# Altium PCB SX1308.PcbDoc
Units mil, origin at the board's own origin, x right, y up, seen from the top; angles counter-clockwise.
Board outline 685 x 570 mil, 2 copper layers (Top Layer, Bottom Layer); 13 components, 7 nets, 30 pads, 24 vias.
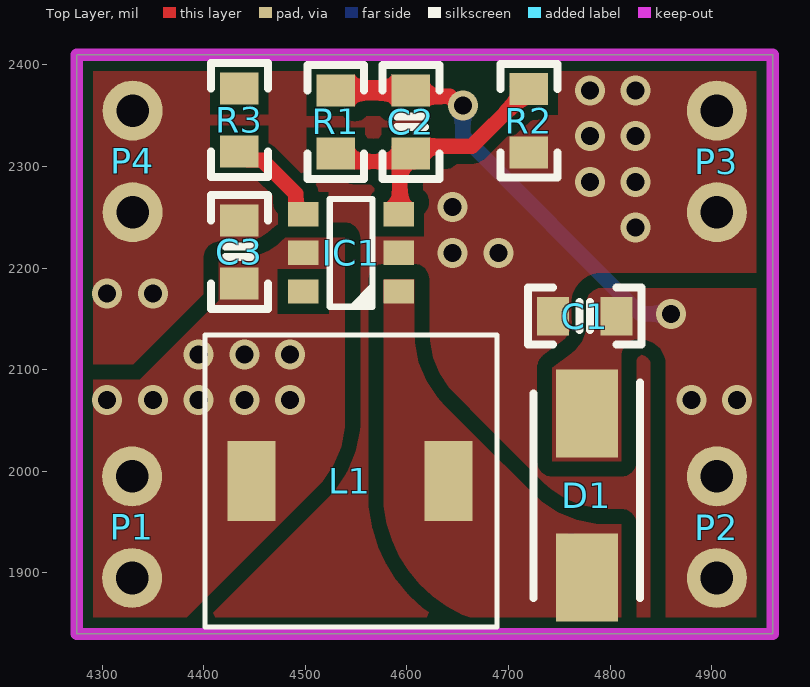
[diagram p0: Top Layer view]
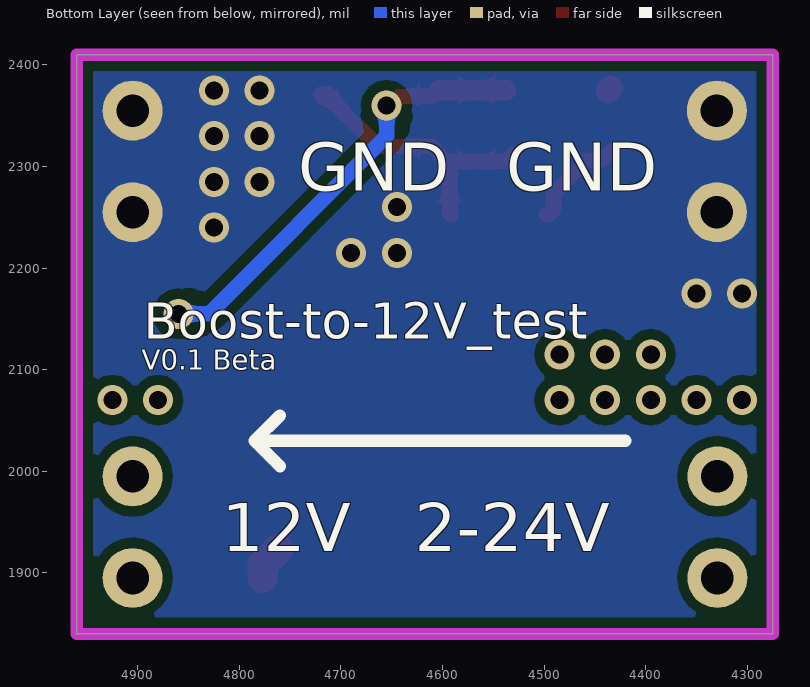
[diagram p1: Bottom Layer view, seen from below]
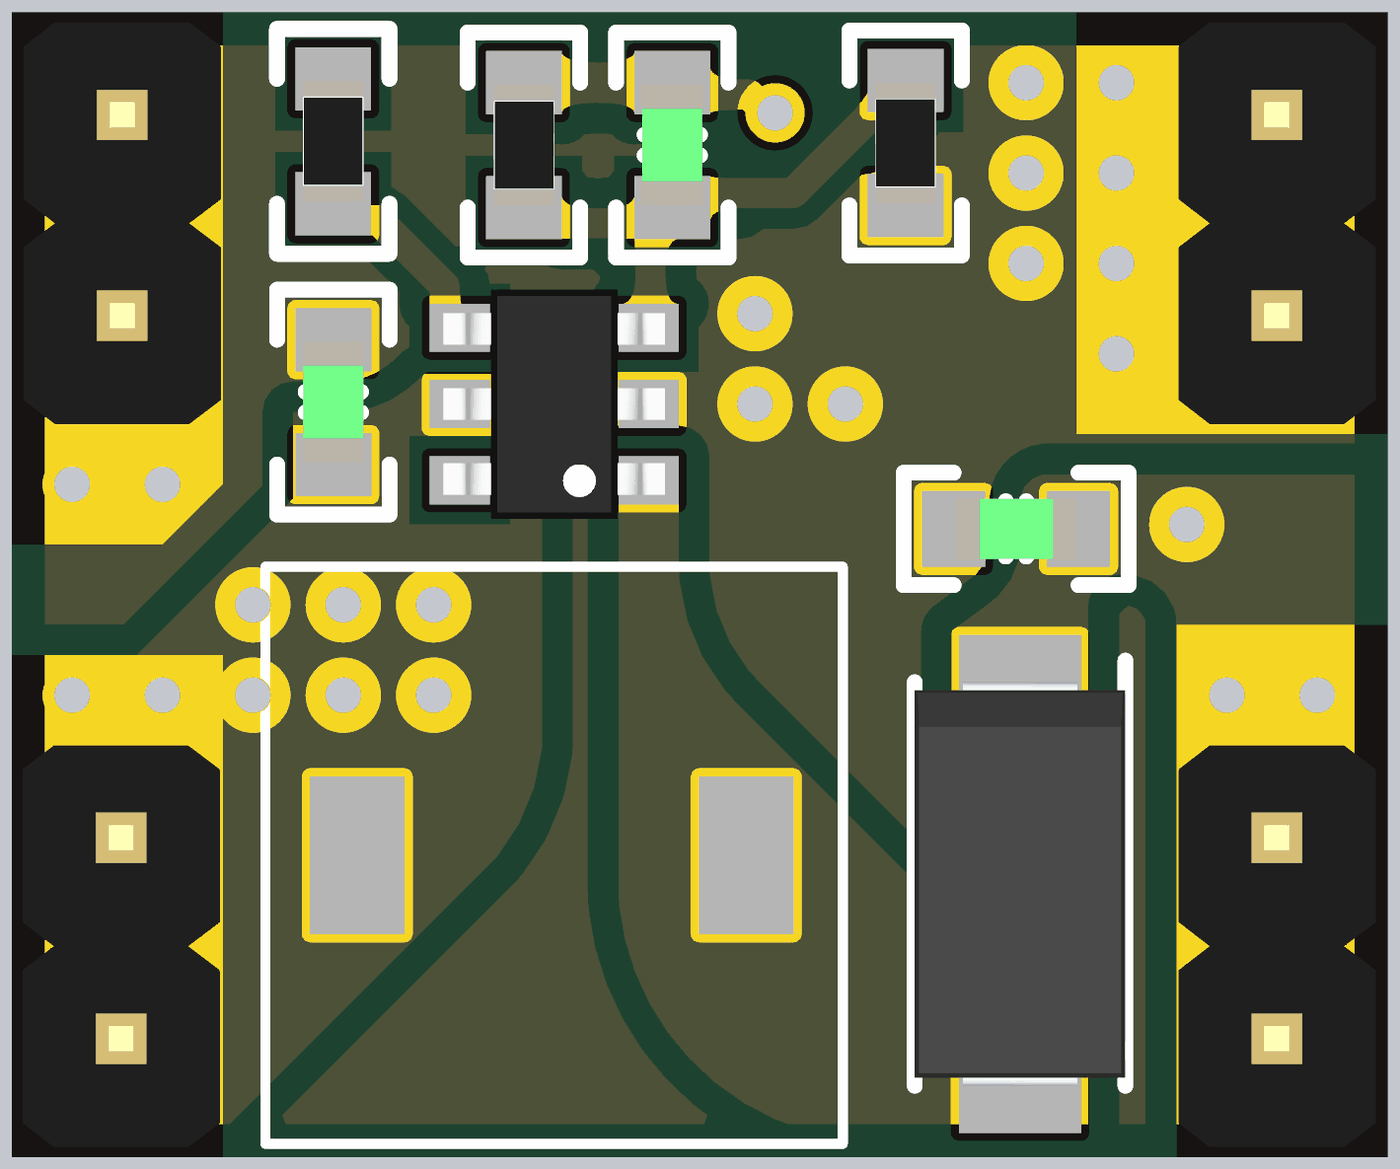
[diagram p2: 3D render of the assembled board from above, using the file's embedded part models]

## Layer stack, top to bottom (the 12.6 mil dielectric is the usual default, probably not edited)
Top Solder: solder mask 0.4, Solder Resist, Dk 3.5
Top Layer: signal copper 1.4
Dielectric 1: dielectric 12.6, FR-4, Dk 4.8
Bottom Layer: signal copper 1.4
Bottom Solder: solder mask 0.4, Solder Resist, Dk 3.5

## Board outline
4275,1840 4960,1840 4960,2410 4275,2410

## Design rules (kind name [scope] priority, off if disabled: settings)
Clearance [All] p1: gap=10 ignorepadtopadclearanceinfootprint=FALSE except(15: Fill-Fill Fill-Poly Fill-Region Poly-Poly Poly-Region Region-Region)
PlaneConnect [All] p1: planeconnectstyle=Direct reliefexpansion=20 reliefentries=4 reliefconductorwidth=10 reliefairgap=10
PolygonConnect [All] p1: connectstyle=Direct reliefconductorwidth=10 reliefentries=4 polygonreliefangle="90 Angle" airgapwidth=10
RoutingVias [All] p1: holewidth=17.72 width=29.53 viastyle="Through Hole" minholewidth=17.72 minwidth=29.53 maxholewidth=17.72 maxwidth=29.53
SolderMaskExpansion [All] p1: expansion=4 istentingtop=FALSE
Width [All] p1: maxlimit=100 minlimit=15 preferedwidth=15
29 further rules are at their usual default settings.

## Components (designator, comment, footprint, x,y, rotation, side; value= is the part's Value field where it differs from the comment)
C1 "22uF/25V" CAP-0603 4775,2152.79 r0 top
C2 "15pF/50V" CAP-0603 4603.83,2343.95 r90 top
C3 "22uF/25V" CAP-0603 4435.05,2215.94 r270 top
D1 "SS34" DO-214AC_SMA 4777,1976 r270 top
IC1 "SX1308" SOT-23-6 4545,2215 r0 top locked
L1 "4.7uH/4A" SMD_7.3x7.3x4.2mm 4526.5,1975.71 r0 top
P1 "HDR1x2_2.54" HDR1X2_2.54_180 4329.46,1995 r0 top
P2 "HDR1x2_2.54" HDR1X2_2.54_180 4905,1995 r0 top
P3 "HDR1x2_2.54" HDR1X2_2.54_180 4905,2355 r0 top
P4 "HDR1x2_2.54" HDR1X2_2.54_180 4330,2355 r0 top
R1 "191k" R-0603 4529.95,2343.95 r90 top
R2 "10k" R-0603 4720,2345 r90 top
R3 "100k" R-0603 4435,2345.82 r270 top

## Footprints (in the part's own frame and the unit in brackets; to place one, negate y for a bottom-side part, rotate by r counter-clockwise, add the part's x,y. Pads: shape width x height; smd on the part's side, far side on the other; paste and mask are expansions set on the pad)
CAP-0603 [mm]
  rect 0.8x0.96 smd: 1(-0.79,0) 2(0.79,0)
  silkscreen extent -1.42,-0.71 1.42,0.71, body extent -0.76,-0.39 0.76,0.39, height 0.9
DO-214AC_SMA [mm]
  rect 2.2x1.55 smd: 1(2.05,0) 2(-2.05,0)
  silkscreen extent -2.83,-1.33 2.55,1.33, body extent -2.55,-1.33 2.55,1.33, height 2.29
HDR1X2_2.54_180 [mm]
  round 1.5 hole 0.813: 1(0,0) 2(0,-2.54)
  body extent -1.25,-3.81 1.25,1.27, height 8.2
R-0603 [mm]
  rect 0.8x0.96 smd: 1(-0.79,0) 2(0.79,0)
  silkscreen extent -1.42,-0.71 1.42,0.71, body extent -0.76,-0.38 0.76,0.38, height 0.41
SMD_7.3x7.3x4.2mm [mm]
  rect 1.2x2 smd: 1(-2.02,0.37) 2(2.9,0.37)
  silkscreen extent -3.18,-3.28 4.12,4.02, body extent -3.18,-3.28 4.1,4, height 3
SOT-23-6 [mil]
  rect 30x24 smd: 1(47,-38) 2(47,0) 3(47,38) 4(-47,38) 5(-47,0) 6(-47,-38)
  silkscreen extent -21,-53 21,53, body extent -55,-57 55,57, height 57

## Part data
C1 C3: library part CAP, "X7R", Package=0402, SuppliersPartNumber=C52923
C2: library part CAP, "NPO", Package=0402, SuppliersPartNumber=C52923
D1: library part DIODE, "肖特基二极管", Package=SMA(DO-214AC), SuppliersPartNumber=C22452
IC1: "集成升压芯片", Manufacturer_Name="Shenzhen Suosemi Tech"
L1: library part INDUCTOR, "电感", Package=0402, SuppliersPartNumber=C32041
P1 P2 P3 P4: "Header"
R1 R2 R3: library part RES, "贴片电阻", Package=0805, SuppliersPartNumber=C17798

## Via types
v1: diameter 29.53, hole 17.72, Top Layer to Bottom Layer, 24 vias

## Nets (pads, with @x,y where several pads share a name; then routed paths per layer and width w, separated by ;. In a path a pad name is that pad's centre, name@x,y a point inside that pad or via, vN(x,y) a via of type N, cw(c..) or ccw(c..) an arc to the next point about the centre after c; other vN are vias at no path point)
5V: C3.2 IC1.5 L1.1 P1.1 P1.2
  other v1: 4305,2070 4350,2070 4395,2070 4440,2070 4485,2070 4395,2115 4440,2115 4485,2115
12V: C1.2 C2.2 D1.2 P2.1 P2.2 R1.2 | length 431.8
  Top Layer w15: C2.2 4609.83,2369.05 4642.02,2369.05 4651.07,2360 v1(4655,2360)
  Top Layer w20: R1.2@4536.95,2375.05 C2.2
  Bottom Layer w15: v1(4655,2360) 4655,2330 4830,2155 v1(4860,2155)
  other v1: 4880,2070 4925,2070
GND: C1.1 C3.1 IC1.2 P3.1 P3.2 P4.1 P4.2 R2.1
  other v1: 4305,2175 4350,2175 4645,2215 4690,2215 4825,2240 4645,2260 4780,2285 4825,2285 4780,2330 4825,2330 4780,2375 4825,2375
NetC2_1: C2.1 IC1.3 R1.1 R2.2 | length 272
  Top Layer w15: R1.1 4537.79,2305 4595.99,2305 C2.1 4610.99,2320 4663.9,2320 4708.6,2364.7 4708.6,2367.85 4711.85,2371.1 R2.2@4720,2371.1 ; IC1.3 4593,2254 C2.1@4593,2302.01
NetD1_1: D1.1 IC1.1 L1.2 | length 34.7
  Top Layer w30: D1.1@4761.49,1923.6 4777,1908.09 D1.1
NetIC1_4: IC1.4 R3.2 | length 97.9
  Top Layer w15: R3.2 4443.25,2306.47 4457.53,2306.47 4490.5,2273.5 4490.5,2257.5 4495,2253 IC1.4
NetR3_1: R3.1 | length 2.7
  Top Layer w25: R3.1 R3.1@4436.92,2375
pads on no net: IC1.6

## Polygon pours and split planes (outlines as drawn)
GND on Top Layer "NONET_L01_P-001" (solid, remove dead copper, pour order 11): 4183,2517 4183,1717 5013,1717 5013,2513
NetD1_1 on Top Layer "NONET_L01_P-001" (solid, pour order 10): 4607,2142 4607,2136.42 ccw(c4707,2136.42) 4636.29,2065.71 4665.85,2036.14 4724.71,1977.29 ccw(c4795.42,2048) 4795.42,1948 4811,1948 4811,1848 4713,1848 cw(c4708,1979) 4577,1974 4577,2189 4607,2189
12V on Top Layer "NONET_L01_P-001" (solid, pour order 9): 4854.61,2109.42 4854.61,1840 4960,1840 4960,2180 4791.25,2180 ccw(c4791.25,2165.75) 4777,2165.75 4777,2151.5 cw(c4740.31,2146.2) 4762.37,2116.41 4743,2102.06 4743,2010 4811,2010 4811,2115 cw(c4826,2115) 4826,2130 4830,2130 cw(c4830,2105)
5V on Top Layer "5V_L01_P001" (solid, remove dead copper, pour order 1): 4539,2121 4539,2053.42 cw(c4439,2053.42) 4509.71,1982.71 4368,1841 4276,1841 4276,2090 4337,2090 4415,2168 4415,2211 4439.1,2211 ccw(c4439.1,2263.88) 4476.49,2226.49 4480,2230 4539,2230
5V on Top Solder "NONET_L01_P-001" (solid): 4275,1840 4380,1840 4380,2090 4275,2090
GND on Top Solder "NONET_L01_P-001" (solid): 4275,2410 4275,2145 4350,2145 4380,2175 4380,2410
GND on Top Solder "NONET_L01_P-001" (solid): 4960,2410 4805,2410 4805,2200 4960,2200
12V on Top Solder "NONET_L01_P-001" (solid): 4855,1840 4960,1840 4960,2105 4855,2105
GND on Bottom Layer "NONET_L01_P-001" (solid, remove dead copper, pour order 12): 4182,1714 4182,1717 5017,1717 5017,2517 4180,2517
no net on Bottom Solder "NONET_L01_P-001" (solid): 4855,1840 4960,1840 4960,2105 4855,2105
no net on Bottom Solder "NONET_L01_P-001" (solid): 4960,2410 4805,2410 4805,2200 4960,2200
no net on Bottom Solder "NONET_L01_P-001" (solid): 4275,2410 4275,2145 4350,2145 4380,2175 4380,2410
no net on Bottom Solder "NONET_L01_P-001" (solid): 4275,1840 4380,1840 4380,2090 4275,2090

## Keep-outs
Keep-Out Layer:
  the board outline again, w12

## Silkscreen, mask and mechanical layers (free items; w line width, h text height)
Bottom Overlay:
  lines w12: 4420,2030 4785,2030 ; 4760,2005 4785,2030 ; 4760,2055 4785,2030
  text "GND" at 4537.13,2276.39 h47.24
  text "GND" at 4742.13,2276.39 h47.24
  text "Boost-to-12V_test" at 4894.09,2130.24 h35.43
  text "V0.1 Beta" at 4896.06,2100.16 h19.68
  text "2-24V" at 4627.13,1921.39 h47.24
  text "12V" at 4817.13,1921.39 h47.24
Mechanical 1:
  the board outline again, w12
